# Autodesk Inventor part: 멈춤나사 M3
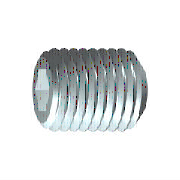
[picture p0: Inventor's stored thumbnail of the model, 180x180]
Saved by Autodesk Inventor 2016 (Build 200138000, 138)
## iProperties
IsCustomPart: 1
Created: 2012-02
Part Number: 멈춤나사 M3
Material: 강철, 연강
Description: 6각 소켓 머리 없는 멈춤 나사
Document SubType Name: Modeling
Standard: KS B 1028
Designer: mduedu
Standards Organization: KS
Language: ko-KR
Size Designation: 납작점M3x8
Categories: <MemberInstance><Categories><Category DisplayName="조임쇠" InternalName="e4da775c-781d-43d5-af7c-5136215cf5a6" Mnemonic="FSTN"><Category DisplayName="볼트" InternalN
Density: 1 g/cm^3
Appearance: 강철
Author: mduedu
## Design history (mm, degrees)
sketch "스케치1"
  geometry: L1 (0, 0)-(5.5, 0); L2 (8, 0.866)-(8, 1.5); L3 (8, 1.5)-(0, 1.5); L4 (8, 0.866)-(6, 0.866); L5 (6, 0.866)-(5.5, 0); L6 (0, -0.3)-(0, 1.8) reference; L7 (0, 1.5)-(0, 0)
  constraints: 13 end point, 3 parallel, 1 collinear, 1 perpendicular, 1 point on line
  dimensions: "d0" = 2 distance of L2.start L4.end (= INTI); "d1" = 60 deg angle of L5 L1; "d2" = 3 diameter of L3 L1 (= NND); "d3" = 1.73205 diameter of L4 L1 (= 1.1547 x SW); "d5" = 8 distance from line of L2 L3.end (= NLG)
revolve "본체" sketch "스케치1" stored, may be unused: angle "d6" = 90 deg
sketch "스케치2"
  geometry: L1 (-0.433, 0.75)-(0.433, 0.75); L2 (0.433, 0.75)-(0.866, 0); L3 (0.866, 0)-(0.433, -0.75); L4 (0.433, -0.75)-(-0.433, -0.75); L5 (-0.433, -0.75)-(-0.866, 0); L6 (-0.866, 0)-(-0.433, 0.75); A1 r 0.866 centre (0, 0) between (-0.433, 0.75) and (0.433, 0.75) reference; 2 further points
  constraints: 12 end point, 2 point on circle, 1 coincident, 1 horizontal, 11 other
extrude "슬롯" join sketch "스케치2" taper "d9" = 0 deg; stored distance "d21" = 10
workaxis "Work Axis1"
workplane "Work Plane1"
body "Solid1"
chamfer "모따기1" distance "d7" = 0.30673 (= -0.5 x GD1 + 0.5 x NND); stored, may be unused: angle "d8" = 45 deg (= FAWI), second distance "d29" = 0.30673 (= -0.5 x GD1 + 0.5 x NND)
feature "스레드" dims "d11" = 8 (= NLG), "d12" = 0
chamfer "모따기2" distance "d13" = 0.30673 (= -0.5 x GD1 + 0.5 x NND); stored, may be unused: angle "d14" = 45 deg (= FAWI), second distance "d30" = 0.30673 (= -0.5 x GD1 + 0.5 x NND)
other parameters: "NND" = 3 [user parameter; used in 5 equation terms], "NLG" = 8 [user parameter; used in 2 equation terms], "INTI" = 2 [user parameter; used in 1 equation term], "FAWI" = 45 deg [user parameter; used in 2 equation terms], "SW" = 1.5 [user parameter; used in 2 equation terms], "GD1" = 2.38655 (= THREADDIA - 1.2269 x PTC) [user parameter; used in 4 equation terms], "d4" = 0, "FAWI1" = 45 deg [user parameter], "d15" = 0, "d31" = 0, "GUL" = 0.30673 (= 0.61345 x PTC) [user parameter], "SPD" = 2 [user parameter], "TOA" = 30 deg [user parameter], "THREADDIA" = 3 [user parameter; used in 1 equation term], "PTC" = 0.5 [user parameter; used in 4 equation terms], "GAL" = 0.30673 (= 0.61345 x PTC) [user parameter], "E0" = 1.7325 (= 1.155 x SW) [user parameter]
